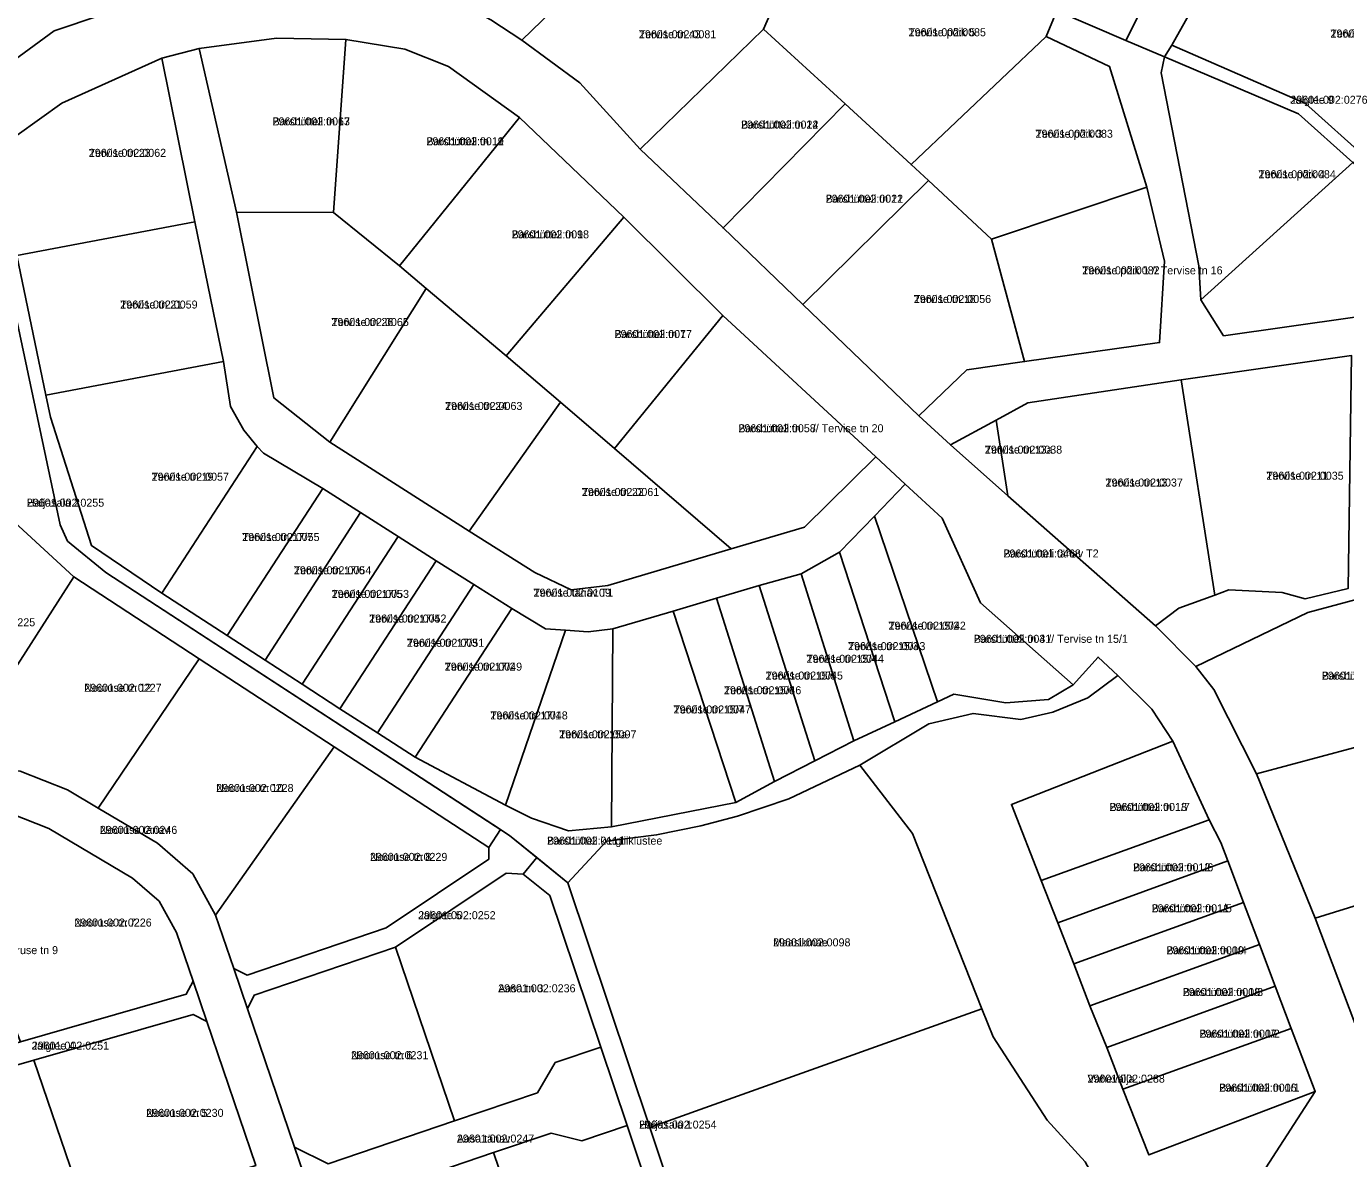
# Model space of a CAD drawing. Extents: x 518839 to 525192, y 6573164 to 6576561.
# Drawn here: x 522397.5 to 522644.9, y 6574633.7 to 6574846 of the extents above; entities that cross this region are included whole.
import ezdxf

# ---------------------------------------------------------------- set-up
doc = ezdxf.new("R2010")
doc.units = 0
for name, color, linetype in [('L_AADRESS', 7, 'Continuous'), ('PIIR', 7, 'Continuous'), ('TUNNUS', 7, 'Continuous')]:
    doc.layers.add(name, color=color, linetype=linetype)

msp = doc.modelspace()

# ---------------------------------------------------------------- linework, layer by layer
at = {"layer": 'PIIR'}
for points in [[(522588.53, 6574886.77), (522596.9, 6574896.56), (522610.95, 6574884.51), (522620.29, 6574876.47), (522603.71, 6574843.35), (522590.75, 6574848.88), (522573.06, 6574856.42)], [(522372.96, 6574880.62), (522397.69, 6574886.36), (522418.62, 6574881.57), (522416.06, 6574872.54), (522420.43, 6574851.14), (522402.75, 6574845.12), (522387, 6574833.63), (522381.66, 6574835.01)], [(522620.29, 6574876.47), (522632.74, 6574879.08), (522625.88, 6574866.61), (522612.32, 6574842.43), (522610.9, 6574840.29), (522603.71, 6574843.35)], [(522545.47, 6574868.19), (522565.67, 6574859.57), (522590.75, 6574848.88), (522588.76, 6574844.1), (522563.41, 6574820.06), (522551.03, 6574831.44), (522535.72, 6574845.42), (522542.16, 6574860.16)], [(522625.88, 6574866.61), (522678.89, 6574839.89), (522680.32, 6574828.97), (522648.95, 6574821.16), (522637.36, 6574831.5), (522612.32, 6574842.43)], [(522505.54, 6574864.52), (522542.16, 6574860.16), (522535.72, 6574845.42), (522512.63, 6574822.97), (522501.34, 6574835.37), (522490.42, 6574843.39), (522503.58, 6574856.12)], [(522429.95, 6574841.84), (522444.41, 6574843.79), (522457.45, 6574843.54), (522455.1, 6574811.07), (522436.95, 6574811.15)], [(522457.45, 6574843.54), (522468.47, 6574841.67), (522476.68, 6574838.46), (522490.01, 6574828.87), (522467.52, 6574801.05), (522455.1, 6574811.07)], [(522512.63, 6574822.97), (522535.72, 6574845.42), (522551.03, 6574831.44), (522528.17, 6574808.2)], [(522563.41, 6574820.06), (522588.76, 6574844.1), (522600.65, 6574838.46), (522607.64, 6574815.83), (522578.49, 6574806.08), (522566.66, 6574817.07)], [(522422.93, 6574840.01), (522429.95, 6574841.84), (522436.95, 6574811.15), (522443.95, 6574776.3), (522454.43, 6574768.02), (522480.56, 6574751.36), (522492.89, 6574743.57), (522499.71, 6574740.33), (522506.55, 6574741.16), (522529.7, 6574748.01), (522543.44, 6574752.07), (522556.78, 6574765.26), (522562.33, 6574760.13), (522556.56, 6574754.17), (522550.01, 6574747.41), (522542.8, 6574743.32), (522534.92, 6574741.14), (522526.91, 6574738.78), (522518.83, 6574736.31), (522507.51, 6574733.02), (522502.88, 6574732.43), (522498.65, 6574732.76), (522494.9, 6574733), (522488.56, 6574736.81), (522481.44, 6574741.34), (522474.38, 6574745.8), (522467.26, 6574750.32), (522460.19, 6574754.83), (522453.11, 6574759.36), (522442, 6574765.98), (522440.84, 6574767.23), (522438.29, 6574770.26), (522435.81, 6574774.7), (522434.49, 6574783.12), (522429.14, 6574809.32)], [(522612.32, 6574842.43), (522637.36, 6574831.5), (522648.95, 6574821.16), (522646.23, 6574820.48), (522636.08, 6574829.55), (522610.9, 6574840.29)], [(522391.57, 6574822.57), (522404.18, 6574831.58), (522422.93, 6574840.01), (522429.14, 6574809.32), (522395.76, 6574803.01)], [(522610.9, 6574840.29), (522636.08, 6574829.55), (522646.23, 6574820.48), (522617.74, 6574794.72), (522617.35, 6574801.05), (522610.32, 6574837.29)], [(522551.03, 6574831.44), (522563.41, 6574820.06), (522566.66, 6574817.07), (522543.15, 6574793.83), (522528.17, 6574808.2)], [(522490.01, 6574828.87), (522509.53, 6574810.22), (522487.51, 6574784.22), (522472.52, 6574796.84), (522467.52, 6574801.05)], [(522375.44, 6574807.59), (522388.11, 6574819.8), (522389.99, 6574817.67), (522403.85, 6574752.49), (522405.28, 6574749.46), (522412.46, 6574743.59), (522486.41, 6574695.39), (522484.23, 6574692.04), (522455.26, 6574710.92), (522429.95, 6574727.42), (522406.42, 6574742.75), (522385.71, 6574761.84), (522379.04, 6574793.83), (522374.59, 6574798.41), (522379.62, 6574803.28)], [(522617.74, 6574794.72), (522646.23, 6574820.48), (522659.43, 6574808.68), (522665.15, 6574806.38), (522658.32, 6574789.32), (522651.13, 6574791.85), (522646.15, 6574791.36), (522622, 6574787.98)], [(522543.15, 6574793.83), (522566.66, 6574817.07), (522578.49, 6574806.08), (522584.69, 6574783.13), (522573.89, 6574781.61), (522564.85, 6574772.97)], [(522578.49, 6574806.08), (522607.64, 6574815.83), (522610.9, 6574801.98), (522610, 6574786.68), (522584.69, 6574783.13)], [(522395.76, 6574803.01), (522429.14, 6574809.32), (522434.49, 6574783.12), (522401.2, 6574776.83)], [(522436.95, 6574811.15), (522455.1, 6574811.07), (522467.52, 6574801.05), (522472.52, 6574796.84), (522454.43, 6574768.02), (522443.95, 6574776.3)], [(522509.53, 6574810.22), (522528.15, 6574791.74), (522507.82, 6574766.86), (522497.66, 6574775.54), (522487.51, 6574784.22)], [(522472.52, 6574796.84), (522487.51, 6574784.22), (522497.66, 6574775.54), (522480.56, 6574751.36), (522454.43, 6574768.02)], [(522528.15, 6574791.74), (522556.78, 6574765.26), (522543.44, 6574752.07), (522529.7, 6574748.01), (522507.82, 6574766.86)], [(522614.06, 6574779.73), (522645.98, 6574784.28), (522645.34, 6574740.58), (522637.28, 6574738.62), (522632.97, 6574739.81), (522622.99, 6574740.32), (522620.38, 6574739.36)], [(522401.2, 6574776.83), (522434.49, 6574783.12), (522435.81, 6574774.7), (522438.29, 6574770.26), (522440.84, 6574767.23), (522422.91, 6574739.72), (522409.77, 6574748.64), (522402.05, 6574772.72)], [(522579.36, 6574772.15), (522585.33, 6574775.4), (522614.06, 6574779.73), (522620.38, 6574739.36), (522613.63, 6574736.87), (522609.22, 6574733.56), (522581.56, 6574757.98)], [(522497.66, 6574775.54), (522507.82, 6574766.86), (522529.7, 6574748.01), (522506.55, 6574741.16), (522499.71, 6574740.33), (522492.89, 6574743.57), (522480.56, 6574751.36)], [(522570.79, 6574767.49), (522579.36, 6574772.15), (522581.56, 6574757.98)], [(522440.84, 6574767.23), (522442, 6574765.98), (522453.11, 6574759.36), (522435.2, 6574731.77), (522422.91, 6574739.72)], [(522385.71, 6574761.84), (522406.42, 6574742.75), (522386.82, 6574712.23), (522386.82, 6574706.87), (522377.59, 6574704.37), (522362.95, 6574736.73), (522368.87, 6574743.25)], [(522453.11, 6574759.36), (522460.19, 6574754.83), (522442.3, 6574727.13), (522435.2, 6574731.77)], [(522562.33, 6574760.13), (522569.24, 6574753.74), (522576.43, 6574737.9), (522593.81, 6574722.53), (522589.16, 6574719.78), (522581.17, 6574719.18), (522571.43, 6574720.78), (522568.36, 6574719.34), (522556.56, 6574754.17)], [(522460.19, 6574754.83), (522467.26, 6574750.32), (522449.22, 6574722.66), (522442.3, 6574727.13)], [(522556.56, 6574754.17), (522568.36, 6574719.34), (522560.39, 6574715.61), (522550.01, 6574747.41)], [(522467.26, 6574750.32), (522474.38, 6574745.8), (522456.33, 6574718.05), (522449.22, 6574722.66)], [(522542.8, 6574743.32), (522550.01, 6574747.41), (522560.39, 6574715.61), (522552.7, 6574712.01)], [(522474.38, 6574745.8), (522481.44, 6574741.34), (522463.39, 6574713.5), (522456.33, 6574718.05)], [(522406.42, 6574742.75), (522429.95, 6574727.42), (522411.01, 6574699.42), (522405.26, 6574702.83), (522396.37, 6574706.34), (522386.82, 6574706.87), (522386.82, 6574712.23)], [(522534.92, 6574741.14), (522542.8, 6574743.32), (522552.7, 6574712.01), (522545.38, 6574708.27)], [(522481.44, 6574741.34), (522488.56, 6574736.81), (522470.44, 6574708.94), (522463.39, 6574713.5)], [(522526.91, 6574738.78), (522534.92, 6574741.14), (522545.38, 6574708.27), (522537.83, 6574704.42)], [(522616.78, 6574725.99), (522637.83, 6574736.11), (522656.87, 6574741.18), (522664.53, 6574715.56), (522628.17, 6574705.81), (522620.17, 6574721.68)], [(522518.83, 6574736.31), (522526.91, 6574738.78), (522537.83, 6574704.42), (522530.54, 6574700.45)], [(522488.56, 6574736.81), (522494.9, 6574733), (522498.65, 6574732.76), (522487.36, 6574699.94), (522470.44, 6574708.94)], [(522507.51, 6574733.02), (522518.83, 6574736.31), (522530.54, 6574700.45), (522507.24, 6574695.93)], [(522498.65, 6574732.76), (522502.88, 6574732.43), (522507.51, 6574733.02), (522507.24, 6574695.93), (522499.2, 6574695.17), (522492.27, 6574697.5), (522487.36, 6574699.94)], [(522429.95, 6574727.42), (522455.26, 6574710.92), (522433.03, 6574679.36), (522428.78, 6574687.06), (522422.12, 6574692.82), (522411.01, 6574699.42)], [(522628.17, 6574705.81), (522664.53, 6574715.56), (522671.55, 6574692.09), (522672.45, 6574689.08), (522639.16, 6574678.8)], [(522455.26, 6574710.92), (522484.23, 6574692.04), (522484.24, 6574689.84), (522464.98, 6574676.96), (522438.96, 6574668.12), (522436.43, 6574669.37), (522433.03, 6574679.36)], [(522582.23, 6574700.1), (522612.5, 6574711.96), (522619.32, 6574697.21), (522587.83, 6574685.81)], [(522506.28, 6574693.2), (522515.69, 6574694.4), (522523.97, 6574696.07), (522530.89, 6574697.93), (522540.5, 6574701.18), (522553.8, 6574707.47), (522563.66, 6574694.64), (522576.69, 6574661.77), (522514.42, 6574639.52), (522499.09, 6574685.4)], [(522380.3, 6574696.81), (522387.66, 6574698.81), (522394.63, 6574698.42), (522401.73, 6574695.62), (522417.43, 6574686.3), (522422.47, 6574681.95), (522425.69, 6574676.12), (522428.79, 6574666.98), (522427.51, 6574664.53), (522396.43, 6574655.61)], [(522436.43, 6574669.37), (522438.96, 6574668.12), (522464.98, 6574676.96), (522484.24, 6574689.84), (522484.23, 6574692.04), (522486.41, 6574695.39), (522488.13, 6574694.27), (522493.22, 6574690.15), (522490.7, 6574687.04), (522487.48, 6574687.19), (522466.76, 6574673.34), (522440.25, 6574664.33), (522439, 6574661.79)], [(522587.83, 6574685.81), (522619.32, 6574697.21), (522621.47, 6574692.96), (522622.79, 6574689.54), (522590.92, 6574677.92)], [(522493.22, 6574690.15), (522499.09, 6574685.4), (522514.42, 6574639.52), (522533.14, 6574583.53), (522534.16, 6574580.68), (522528.34, 6574581.76), (522526.64, 6574586.47), (522527.81, 6574586.89), (522510.2, 6574639.9), (522505.24, 6574654.59), (522495.66, 6574683.02), (522490.7, 6574687.04)], [(522590.92, 6574677.92), (522622.79, 6574689.54), (522625.75, 6574681.7), (522593.93, 6574670.24)], [(522639.16, 6574678.8), (522672.45, 6574689.08), (522678.6, 6574668.54), (522680.03, 6574663.75), (522655.16, 6574655.6), (522648.72, 6574653.48)], [(522466.76, 6574673.34), (522487.48, 6574687.19), (522490.7, 6574687.04), (522495.66, 6574683.02), (522505.24, 6574654.59), (522496.71, 6574651.69), (522493.35, 6574646.06), (522477.82, 6574640.78)], [(522593.93, 6574670.24), (522625.75, 6574681.7), (522628.74, 6574673.82), (522596.96, 6574662.33)], [(522440.25, 6574664.33), (522466.76, 6574673.34), (522477.82, 6574640.78), (522454.15, 6574632.74), (522447.81, 6574635.87), (522439, 6574661.79)], [(522596.96, 6574662.33), (522628.74, 6574673.82), (522631.7, 6574666.01), (522600.09, 6574654.53)], [(522365.78, 6574648.89), (522368.32, 6574647.54), (522396.43, 6574655.61), (522427.51, 6574664.53), (522428.79, 6574666.98), (522431.37, 6574659.4), (522428.8, 6574660.74), (522398.97, 6574652.18), (522369.57, 6574643.74), (522368.27, 6574641.29)], [(522600.09, 6574654.53), (522631.7, 6574666.01), (522634.7, 6574658.12), (522603.15, 6574646.72)], [(522398.97, 6574652.18), (522428.8, 6574660.74), (522431.37, 6574659.4), (522440.54, 6574632.39), (522409.11, 6574622.32)], [(522514.42, 6574639.52), (522576.69, 6574661.77), (522578.8, 6574656.51), (522588.95, 6574640.93), (522596.06, 6574633.1), (522606.23, 6574614.52), (522533.14, 6574583.53)], [(522603.15, 6574646.72), (522634.7, 6574658.12), (522639.18, 6574646.29), (522607.98, 6574634.38)], [(522447.81, 6574635.87), (522454.15, 6574632.74), (522477.82, 6574640.78), (522493.35, 6574646.06), (522496.71, 6574651.69), (522505.24, 6574654.59), (522510.2, 6574639.9), (522501.7, 6574637.01), (522495.92, 6574638.48), (522485.13, 6574634.82), (522456.73, 6574625.16), (522453.6, 6574618.82)], [(522369.57, 6574643.74), (522398.97, 6574652.18), (522409.11, 6574622.32), (522375.42, 6574611.51), (522369.6, 6574637.23), (522368.27, 6574641.29)], [(522485.13, 6574634.82), (522495.92, 6574638.48), (522501.7, 6574637.01), (522510.2, 6574639.9), (522527.81, 6574586.89), (522526.64, 6574586.47), (522504.31, 6574578.38), (522495.43, 6574604.52)], [(522456.73, 6574625.16), (522485.13, 6574634.82), (522495.43, 6574604.52), (522462.29, 6574593.26), (522453.6, 6574618.82)]]:
    msp.add_lwpolyline(points, close=True, dxfattribs=at)
for points in [[(522503.58, 6574856.12), (522490.42, 6574843.39), (522484.64, 6574847.21)], [(522387, 6574833.63), (522402.75, 6574845.12), (522420.43, 6574851.14), (522427.3, 6574852.93), (522438.54, 6574855.26), (522447.43, 6574855.49), (522457.99, 6574855.32), (522468.36, 6574853.48), (522476.2, 6574851.79), (522484.64, 6574847.21), (522490.42, 6574843.39), (522501.34, 6574835.37), (522512.63, 6574822.97), (522528.17, 6574808.2), (522543.15, 6574793.83), (522564.85, 6574772.97), (522570.79, 6574767.49), (522581.56, 6574757.98), (522609.22, 6574733.56), (522616.78, 6574725.99), (522620.17, 6574721.68), (522628.17, 6574705.81), (522639.16, 6574678.8), (522648.72, 6574653.48)], [(522645.98, 6574784.28), (522614.06, 6574779.73), (522585.33, 6574775.4), (522579.36, 6574772.15), (522570.79, 6574767.49), (522564.85, 6574772.97), (522573.89, 6574781.61), (522584.69, 6574783.13), (522610, 6574786.68), (522610.9, 6574801.98), (522607.64, 6574815.83), (522600.65, 6574838.46), (522588.76, 6574844.1), (522590.75, 6574848.88), (522603.71, 6574843.35), (522610.9, 6574840.29), (522610.32, 6574837.29), (522617.35, 6574801.05), (522617.74, 6574794.72), (522622, 6574787.98), (522646.15, 6574791.36)], [(522623.33, 6574621.73), (522639.18, 6574646.29), (522634.7, 6574658.12), (522631.7, 6574666.01), (522628.74, 6574673.82), (522625.75, 6574681.7), (522622.79, 6574689.54), (522621.47, 6574692.96), (522619.32, 6574697.21), (522612.5, 6574711.96), (522608.55, 6574717.96), (522602.19, 6574724.27), (522598.47, 6574727.72), (522593.81, 6574722.53), (522576.43, 6574737.9), (522569.24, 6574753.74), (522562.33, 6574760.13), (522556.78, 6574765.26), (522528.15, 6574791.74), (522509.53, 6574810.22), (522490.01, 6574828.87), (522476.68, 6574838.46), (522468.47, 6574841.67), (522457.45, 6574843.54), (522444.41, 6574843.79), (522429.95, 6574841.84), (522422.93, 6574840.01), (522404.18, 6574831.58), (522391.57, 6574822.57)], [(522395.76, 6574803.01), (522401.2, 6574776.83), (522402.05, 6574772.72), (522409.77, 6574748.64), (522422.91, 6574739.72), (522435.2, 6574731.77), (522442.3, 6574727.13), (522449.22, 6574722.66), (522456.33, 6574718.05), (522463.39, 6574713.5), (522470.44, 6574708.94), (522487.36, 6574699.94), (522492.27, 6574697.5), (522499.2, 6574695.17), (522507.24, 6574695.93), (522530.54, 6574700.45), (522537.83, 6574704.42), (522545.38, 6574708.27), (522552.7, 6574712.01), (522560.39, 6574715.61), (522568.36, 6574719.34), (522571.43, 6574720.78), (522581.17, 6574719.18), (522589.16, 6574719.78), (522593.81, 6574722.53), (522598.47, 6574727.72), (522602.19, 6574724.27), (522596.58, 6574720.08), (522589.99, 6574717.37), (522583.97, 6574716.01), (522575.04, 6574717.15), (522566.73, 6574715.21), (522553.8, 6574707.47), (522540.5, 6574701.18), (522530.89, 6574697.93), (522523.97, 6574696.07), (522515.69, 6574694.4), (522506.28, 6574693.2), (522499.09, 6574685.4), (522488.13, 6574694.27), (522412.46, 6574743.59), (522405.28, 6574749.46), (522403.85, 6574752.49), (522389.99, 6574817.67)], [(522656.87, 6574741.18), (522637.83, 6574736.11), (522616.78, 6574725.99), (522609.22, 6574733.56), (522613.63, 6574736.87), (522620.38, 6574739.36), (522622.99, 6574740.32), (522632.97, 6574739.81), (522637.28, 6574738.62), (522645.34, 6574740.58)], [(522596.06, 6574633.1), (522588.95, 6574640.93), (522578.8, 6574656.51), (522576.69, 6574661.77), (522563.66, 6574694.64), (522553.8, 6574707.47), (522566.73, 6574715.21), (522575.04, 6574717.15), (522583.97, 6574716.01), (522589.99, 6574717.37), (522596.58, 6574720.08), (522602.19, 6574724.27), (522608.55, 6574717.96), (522612.5, 6574711.96), (522582.23, 6574700.1), (522587.83, 6574685.81), (522590.92, 6574677.92), (522593.93, 6574670.24), (522596.96, 6574662.33), (522600.09, 6574654.53), (522603.15, 6574646.72), (522607.98, 6574634.38), (522639.18, 6574646.29), (522623.33, 6574621.73)], [(522396.37, 6574706.34), (522405.26, 6574702.83), (522411.01, 6574699.42), (522422.12, 6574692.82), (522428.78, 6574687.06), (522433.03, 6574679.36), (522436.43, 6574669.37), (522439, 6574661.79), (522447.81, 6574635.87), (522453.6, 6574618.82)], [(522440.54, 6574632.39), (522431.37, 6574659.4), (522428.79, 6574666.98), (522425.69, 6574676.12), (522422.47, 6574681.95), (522417.43, 6574686.3), (522401.73, 6574695.62), (522394.63, 6574698.42)]]:
    msp.add_lwpolyline(points, dxfattribs=at)

# ---------------------------------------------------------------- texts
at = {"layer": 'L_AADRESS'}
for s, p in [('Tervise tn 43', (522512.39, 6574843.74)), ('Tervise põik 5', (522562.95, 6574844.12)), ('Tervise põik 6', (522642.05, 6574843.88)), ('Jalgtee 9', (522634.51, 6574831.46)), ('Barsbütteli tn 13', (522443.7, 6574827.41)), ('Barsbütteli tn 14', (522531.53, 6574826.81)), ('Tervise põik 3', (522586.75, 6574825.09)), ('Barsbütteli tn 11', (522472.55, 6574823.68)), ('Tervise tn 23', (522409.24, 6574821.51)), ('Tervise põik 4', (522628.55, 6574817.5)), ('Barsbütteli tn 12', (522547.41, 6574812.91)), ('Barsbütteli tn 9', (522488.53, 6574806.23)), ('Tervise põik 1 // Tervise tn 16', (522595.51, 6574799.48)), ('Tervise tn 21', (522415.14, 6574793.07)), ('Tervise tn 18', (522563.92, 6574794.11)), ('Tervise tn 26', (522454.74, 6574789.79)), ('Barsbütteli tn 7', (522507.83, 6574787.54)), ('Tervise tn 24', (522476.04, 6574774.06)), ('Barsbütteli tn 5 // Tervise tn 20', (522531.04, 6574769.88)), ('Tervise tn 13a', (522577.24, 6574765.87)), ('Tervise tn 19', (522421.02, 6574760.79)), ('Tervise tn 11', (522630.02, 6574760.98)), ('Tervise tn 22', (522501.69, 6574757.93)), ('Tervise tn 13', (522599.87, 6574759.7)), ('Haljasala 2', (522397.63, 6574755.92)), ('Tervise tn 17/7', (522438.01, 6574749.49)), ('Barsbütteli tänav T2', (522580.74, 6574746.4)), ('Tervise tn 17/6', (522447.7, 6574743.25)), ('Tervise tn 17/5', (522454.78, 6574738.82)), ('Tervise tänav T1', (522492.63, 6574739.05)), ('Tervise tn 17/4', (522461.8, 6574734.2)), ('Tervise tn 15/2', (522559.18, 6574732.86)), ('Tervise tn 17/3', (522468.88, 6574729.66)), ('Tervise tn 15/3', (522551.59, 6574729.03)), ('Barsbütteli tn 3 // Tervise tn 15/1', (522575.19, 6574730.4)), ('Tervise tn 15/4', (522543.81, 6574726.66)), ('Tervise tn 17/2', (522475.98, 6574725.18)), ('Tervise tn 15/5', (522536.14, 6574723.51)), ('Barsbütteli tn 6', (522640.45, 6574723.49)), ('Nooruse tn 12', (522408.39, 6574721.22)), ('Tervise tn 15/6', (522528.33, 6574720.76)), ('Tervise tn 17/1', (522484.54, 6574716.04)), ('Tervise tn 15/7', (522518.89, 6574717.16)), ('Tervise tn 15a', (522497.43, 6574712.5)), ('Nooruse tn 10', (522433.13, 6574702.43)), ('Barsbütteli tn 1/7', (522600.63, 6574698.88)), ('Nooruse tänav', (522411.33, 6574694.58)), ('Barsbütteli kergliiklustee', (522495.15, 6574692.56)), ('Nooruse tn 8', (522461.97, 6574689.52)), ('Barsbütteli tn 1/6', (522605.03, 6574687.57)), ('Jalgtee 5', (522471.02, 6574678.59)), ('Barsbütteli tn 1/5', (522608.52, 6574679.89)), ('Nooruse tn 7', (522406.53, 6574677.21)), ('Barsbütteli tn 23 // Nooruse tn 9', (522375.27, 6574672.04)), ('Maasikmäe', (522537.55, 6574673.49)), ('Barsbütteli tn 1/4', (522611.3, 6574672.01)), ('Aasa tn 3', (522486, 6574664.88)), ('Barsbütteli tn 1/3', (522614.36, 6574664.18)), ('Barsbütteli tn 1/2', (522617.49, 6574656.37)), ('Jalgtee 4', (522398.54, 6574654.13)), ('Nooruse tn 6', (522458.41, 6574652.34)), ('Vahevälja', (522596.49, 6574647.94)), ('Barsbütteli tn 1/1', (522621.2, 6574646.25)), ('Nooruse tn 5', (522420.01, 6574641.53)), ('Haljasala 1', (522512.43, 6574639.33)), ('Aasa tänav', (522478.26, 6574636.71))]:
    msp.add_text(s, height=1.5, dxfattribs=at).set_placement(p)
at = {"layer": 'TUNNUS'}
for s, p in [('29601:002:0081', (522512.39, 6574843.74)), ('29601:002:0085', (522562.95, 6574844.12)), ('29601:002:0262', (522642.05, 6574843.88)), ('29601:002:0276', (522634.51, 6574831.46)), ('29601:002:0067', (522443.7, 6574827.41)), ('29601:002:0022', (522531.53, 6574826.81)), ('29601:002:0083', (522586.75, 6574825.09)), ('29601:002:0019', (522472.55, 6574823.68)), ('29601:002:0062', (522409.24, 6574821.51)), ('29601:002:0084', (522628.55, 6574817.5)), ('29601:002:0021', (522547.41, 6574812.91)), ('29601:002:0018', (522488.53, 6574806.23)), ('29601:002:0082', (522595.51, 6574799.48)), ('29601:002:0059', (522415.14, 6574793.07)), ('29601:002:0056', (522563.92, 6574794.11)), ('29601:002:0065', (522454.74, 6574789.79)), ('29601:002:0017', (522507.83, 6574787.54)), ('29601:002:0063', (522476.04, 6574774.06)), ('29601:002:0058', (522531.04, 6574769.88)), ('29601:002:0038', (522577.24, 6574765.87)), ('29601:002:0057', (522421.02, 6574760.79)), ('29601:002:0035', (522630.02, 6574760.98)), ('29601:002:0061', (522501.69, 6574757.93)), ('29601:002:0037', (522599.87, 6574759.7)), ('29601:002:0255', (522397.63, 6574755.92)), ('29601:002:0055', (522438.01, 6574749.49)), ('29601:001:0468', (522580.74, 6574746.4)), ('29601:002:0054', (522447.7, 6574743.25)), ('29601:002:0053', (522454.78, 6574738.82)), ('29601:002:0109', (522492.63, 6574739.05)), ('29601:002:0225', (522384.69, 6574733.5)), ('29601:002:0052', (522461.8, 6574734.2)), ('29601:002:0042', (522559.18, 6574732.86)), ('29601:002:0051', (522468.88, 6574729.66)), ('29601:002:0043', (522551.59, 6574729.03)), ('29601:002:0041', (522575.19, 6574730.4)), ('29601:002:0044', (522543.81, 6574726.66)), ('29601:002:0049', (522475.98, 6574725.18)), ('29601:002:0045', (522536.14, 6574723.51)), ('29601:002:0016', (522640.45, 6574723.49)), ('29601:002:0227', (522408.39, 6574721.22)), ('29601:002:0046', (522528.33, 6574720.76)), ('29601:002:0048', (522484.54, 6574716.04)), ('29601:002:0047', (522518.89, 6574717.16)), ('29601:002:0097', (522497.43, 6574712.5)), ('29601:002:0228', (522433.13, 6574702.43)), ('29601:002:0013', (522600.63, 6574698.88)), ('29601:002:0246', (522411.33, 6574694.58)), ('29601:002:0111', (522495.15, 6574692.56)), ('29601:002:0229', (522461.97, 6574689.52)), ('29601:002:0012', (522605.03, 6574687.57)), ('29601:002:0252', (522471.02, 6574678.59)), ('29601:002:0011', (522608.52, 6574679.89)), ('29601:002:0226', (522406.53, 6574677.21)), ('29601:002:0098', (522537.55, 6574673.49)), ('29601:002:0009', (522611.3, 6574672.01)), ('29601:002:0236', (522486, 6574664.88)), ('29601:002:0008', (522614.36, 6574664.18)), ('29601:002:0007', (522617.49, 6574656.37)), ('29601:002:0251', (522398.54, 6574654.13)), ('29601:002:0231', (522458.41, 6574652.34)), ('29601:002:0288', (522596.49, 6574647.94)), ('29601:002:0006', (522621.2, 6574646.25)), ('29601:002:0230', (522420.01, 6574641.53)), ('29601:002:0254', (522512.43, 6574639.33)), ('29601:002:0247', (522478.26, 6574636.71))]:
    msp.add_text(s, height=1.5, dxfattribs=at).set_placement(p)

doc.saveas('drawing.dxf')
